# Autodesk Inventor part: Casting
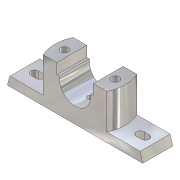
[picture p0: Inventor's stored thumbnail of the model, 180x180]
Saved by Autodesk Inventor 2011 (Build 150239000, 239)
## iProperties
Shininess: 77.0
Length Units: 11269
Angle Units: 11279
Time Units: 11290
Mass Units: 11283
Length Display Precision: 3
Angle Display Precision: 2
Created: 2002-02
Part Number: Casting
Document SubType Name: Modeling
Designer: ***
Density: 1 g/cm^3
Density: 0.0
Volumn: 0.0
Area: 0.0
PropertySet Name: Model Information
Control State: 0
Master: False
Checked Out: False
Author: ***
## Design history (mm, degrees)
sketch "Sketch2"
  geometry: L1 (113.55, -33.109)-(-94.45, -33.109); L2 (-94.45, -33.109)-(-90.45, -19.109); L3 (-90.45, -19.109)-(-50.45, -19.109); L4 (-50.45, -19.109)-(-50.45, 34.891); L5 (-50.45, 34.891)-(-18.45, 34.891); L6 (-18.45, 34.891)-(-18.45, 18.891); L7 (-18.45, 18.891)-(-14.45, 18.891); L8 (-14.45, 18.891)-(-14.45, 14.891); L9 (37.55, 18.891)-(33.55, 18.891); L10 (37.55, 34.891)-(37.55, 18.891); L11 (69.55, 34.891)-(37.55, 34.891); L12 (69.55, -19.109)-(69.55, 34.891); L13 (109.55, -19.109)-(69.55, -19.109); L14 (113.55, -33.109)-(109.55, -19.109); L15 (33.55, 18.891)-(33.55, 14.891); A1 r 24 centre (9.55, 14.891) between (-14.45, 14.891) and (33.55, 14.891)
  constraints: 30 end point, 7 equal length, 5 parallel, 3 horizontal, 2 point on circle, 2 tangent, 2 vertical, 1 centre point, 1 horizontal alignment, 1 perpendicular, 1 vertical alignment
  dimensions: "d0" = 208 distance of L1.start L1.end; "d1" = 56 distance between parallel lines of L6 L10; "d2" = 24 radius of A1; "d3" = 4 distance of L8.end L7.end; "d4" = 16 distance from line of L5 L7.end; "d5" = 14 distance between parallel lines of L3 L1; "d6" = 4 horizontal distance of L1.start L13.start; "d7" = 120 distance between parallel lines of L4 L12; "d15" = 54 distance between parallel lines of L11 L13
extrude "Extrusion1" new body sketch "Sketch2" stored distance "d8" = 46; taper "d9" = 0 deg
sketch "Sketch4"
  geometry: L1 (0, 0)-(0, -46) reference; L2 (0, 0)-(11.143, 0); L3 (0, -46)-(11.143, -46); L4 (120, 0)-(108.857, 0); L5 (120, 0)-(120, -46); L6 (120, -46)-(108.857, -46); A1 r 54 centre (60, -23) between (11.143, 0) and (11.143, -46); A2 r 54 centre (60, -23) between (108.857, -46) and (108.857, 0)
  constraints: 10 end point, 4 point on circle, 2 centre point, 1 parallel
extrude "Extrusion2" cut sketch "Sketch4" distance "d13" = 54; taper "d14" = 0 deg
sketch "Sketch5"
  geometry: L1 (-51.143, 0)-(0, 0) reference; L2 (0, 46)-(0, 0) reference; L3 (-23, 29)-(-15, 29); L4 (-15, 17)-(-23, 17); A1 r 6 centre (-15, 23) between (-15, 17) and (-15, 29); A2 r 6 centre (-23, 23) between (-23, 29) and (-23, 17)
  constraints: 4 end point, 4 point on circle, 3 tangent, 2 centre point, 1 parallel, 1 perpendicular
  dimensions: "d16" = 8 distance of L4.start L4.end; "d17" = 6 radius of A1; "d18" = 23 distance from line of L1 A1.centre; "d19" = 15 distance from line of L2 A1.centre
extrude "Extrusion3" cut sketch "Sketch5" stored distance "d20" = 46; taper "d21" = 0 deg
sketch "Sketch6"
  geometry: L1 (76, 46)-(76, 0) reference; L2 (0, 0)-(20.857, 0) reference; C1 r 6 at (11, 23)
  constraints: 1 centre point
  dimensions: "d22" = 12 diameter of C1; "d23" = 65 distance from line of L1 C1.centre; "d24" = 23 distance from line of L2 C1.centre
extrude "Extrusion4" cut sketch "Sketch6" stored distance "d25" = 46; taper "d26" = 0 deg
sketch "Sketch7"
  geometry: L1 (78, -36)-(52, -36); L2 (52, -36)-(52, -10); L3 (52, -10)-(78, -10); L4 (78, -10)-(78, -36); C1 r 6 at (65, -23) reference
  constraints: 8 end point, 2 parallel, 2 perpendicular, 1 horizontal
  dimensions: "d27" = 26 distance of L1.start L1.end; "d28" = 13 distance from line of C1.centre L1; "d29" = 13 distance from line of L2 C1.centre
extrude "Extrusion5" cut sketch "Sketch7" distance "d30" = 10; taper "d31" = 0 deg
workplane "Work Plane1"
workplane "Work Plane2"
mirror "Mirror1"
workplane "Work Plane3"
sketch "Sketch8"
  geometry: C1 r 4 at (0, 0)
  constraints: 1 centre point
  dimensions: "d34" = 8 diameter of C1
extrude "Extrusion6" cut sketch "Sketch8" stored distance "d35" = 16; taper "d36" = 0 deg
body "Solid1"
other parameters: "d32" = 90 deg, "d33" = -104
